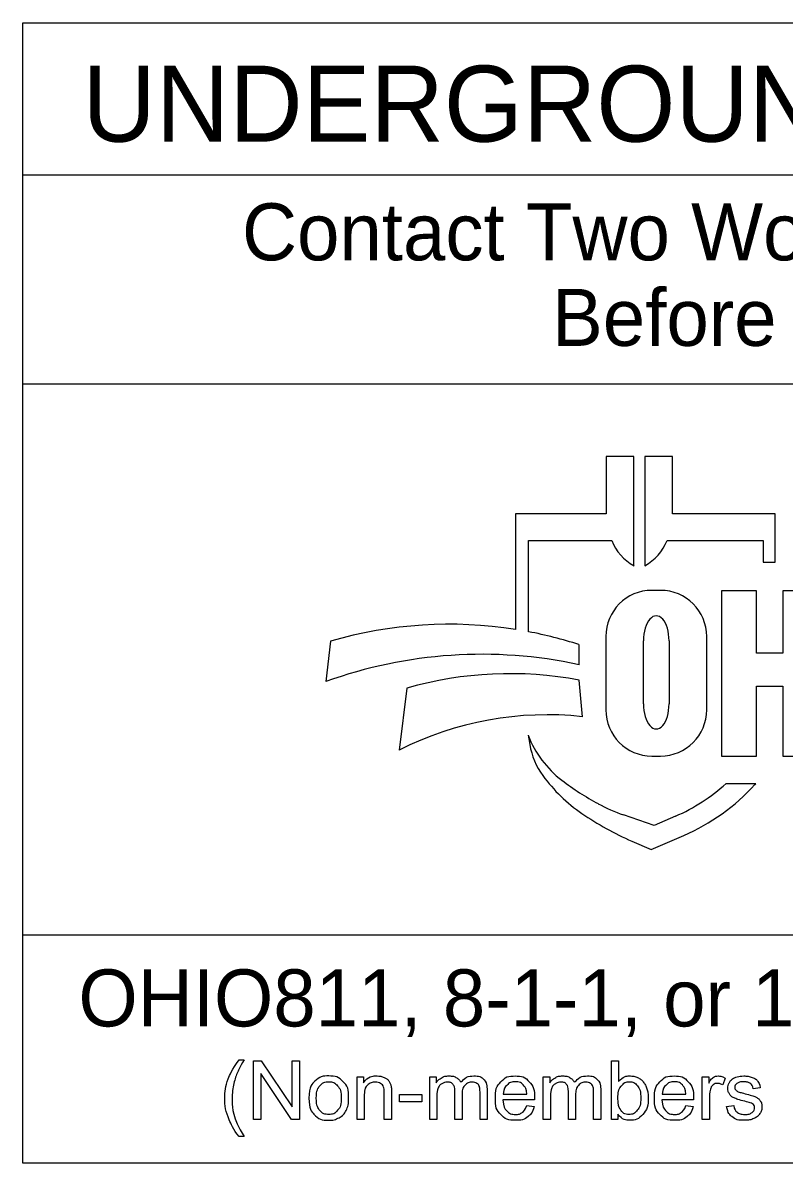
# Model space of a CAD drawing. Extents: x 0 to 34, y 0 to 22.
# Drawn here: x 3.242 to 5.246, y 2.235 to 5.235 of the extents above; entities that cross this region are included whole.
import ezdxf

# ---------------------------------------------------------------- set-up
doc = ezdxf.new("R2010")
doc.units = 0
doc.layers.add('SH_Data', color=7, linetype='Continuous')

msp = doc.modelspace()

# ---------------------------------------------------------------- linework, layer by layer
at = {"layer": 'SH_Data'}
for p, q in [((3.2423, 5.2348), (7.9923, 5.2348)), ((3.2423, 2.2348), (3.2423, 5.2348)), ((3.2423, 4.8348), (7.9923, 4.8348)), ((3.2423, 4.2848), (7.9923, 4.2848)), ((4.8504, 4.0943), (4.7776, 4.0943)), ((4.7776, 4.0943), (4.7776, 3.9429)), ((4.8504, 3.8063), (4.8504, 4.0943)), ((4.9515, 4.0943), (4.8787, 4.0943)), ((4.8787, 4.0943), (4.8787, 3.8063)), ((4.9515, 3.9429), (4.9515, 4.0943)), ((4.7776, 3.9429), (4.5386, 3.9429)), ((4.5386, 3.9429), (4.5386, 3.6389)), ((5.2221, 3.9429), (4.9515, 3.9429)), ((5.2221, 3.8155), (5.2221, 3.9429)), ((4.5729, 3.6329), (4.5729, 3.873)), ((4.5729, 3.873), (4.7917, 3.873)), ((4.9374, 3.873), (5.1905, 3.873)), ((5.1905, 3.873), (5.1905, 3.8155)), ((5.1905, 3.8155), (5.2221, 3.8155)), ((4.9202, 3.7418), (4.8977, 3.7418)), ((5.1728, 3.7405), (5.0805, 3.7405)), ((5.0805, 3.7405), (5.0805, 3.3059)), ((4.0522, 3.6078), (4.0395, 3.5017)), ((4.7762, 3.6203), (4.7762, 3.4274)), ((4.8752, 3.4429), (4.8752, 3.6091)), ((4.9428, 3.6091), (4.9428, 3.4429)), ((5.0417, 3.4274), (5.0417, 3.6203)), ((4.7058, 3.5462), (4.7058, 3.599)), ((4.2528, 3.4848), (4.2328, 3.3217)), ((4.715, 3.4094), (4.7065, 3.5058)), ((5.1728, 3.3059), (5.1728, 3.4897)), ((4.572, 3.3606), (4.5762, 3.3363)), ((4.8977, 3.3059), (4.9202, 3.3059)), ((5.0805, 3.3059), (5.1728, 3.3059)), ((5.1706, 3.2332), (5.0926, 3.2332)), ((5.1684, 3.2308), (5.1706, 3.2332)), ((4.9038, 3.1234), (4.8231, 3.1512)), ((4.9596, 3.1476), (4.9038, 3.1234)), ((4.8957, 3.0596), (4.9816, 3.0968)), ((4.8449, 3.0819), (4.8957, 3.0596)), ((7.9923, 2.8348), (3.2423, 2.8348)), ((7.9923, 2.2348), (3.2423, 2.2348))]:
    msp.add_line(p, q, dxfattribs=at)
for points in [[(5.1728, 3.4897), (5.242, 3.4897), (5.242, 3.3059), (5.3343, 3.3059), (5.3343, 3.7405), (5.242, 3.7405), (5.242, 3.5766), (5.1728, 3.5766), (5.1728, 3.7405)], [(3.8112, 2.5067), (3.8247, 2.5067)], [(3.8489, 2.3501), (3.8489, 2.5041), (3.8698, 2.5041), (3.9508, 2.3832), (3.9508, 2.5041), (3.9703, 2.5041), (3.9703, 2.3501), (3.9494, 2.3501), (3.8684, 2.4711), (3.8684, 2.3501), (3.8489, 2.3501)], [(4.8083, 2.3501), (4.7909, 2.3501), (4.7909, 2.5041), (4.8098, 2.5041), (4.8098, 2.4493)], [(4.1217, 2.3501), (4.1217, 2.4618), (4.1387, 2.4618), (4.1387, 2.4459)], [(4.3129, 2.3501), (4.3129, 2.4618), (4.3298, 2.4618), (4.3298, 2.446)], [(4.6117, 2.3501), (4.6117, 2.4618), (4.6286, 2.4618), (4.6286, 2.446)], [(5.03, 2.3501), (5.03, 2.4618), (5.047, 2.4618), (5.047, 2.4449)], [(5.0905, 2.4582), (5.0839, 2.4407)], [(5.1828, 2.4329), (5.1642, 2.4304)], [(4.1406, 2.411), (4.1406, 2.3501), (4.1217, 2.3501)], [(4.2123, 2.4187), (4.2123, 2.3501), (4.1934, 2.3501), (4.1934, 2.418)], [(4.2338, 2.3964), (4.2338, 2.4154), (4.292, 2.4154), (4.292, 2.3964), (4.2338, 2.3964)], [(4.3318, 2.408), (4.3318, 2.3501), (4.3129, 2.3501)], [(4.3981, 2.4149), (4.3981, 2.3501), (4.3792, 2.3501), (4.3792, 2.4226)], [(4.4642, 2.4267), (4.4642, 2.3501), (4.4453, 2.3501), (4.4453, 2.4204)], [(4.5885, 2.4011), (4.5053, 2.4011)], [(4.5063, 2.4166), (4.5687, 2.4166)], [(4.6306, 2.408), (4.6306, 2.3501), (4.6117, 2.3501)], [(4.6969, 2.4149), (4.6969, 2.3501), (4.678, 2.3501), (4.678, 2.4226)], [(4.763, 2.4267), (4.763, 2.3501), (4.7441, 2.3501), (4.7441, 2.4204)], [(5.007, 2.4011), (4.9237, 2.4011)], [(4.9248, 2.4166), (4.9871, 2.4166)], [(5.0489, 2.4086), (5.0489, 2.3501), (5.03, 2.3501)], [(4.5684, 2.3862), (4.588, 2.3837)], [(4.9869, 2.3862), (5.0064, 2.3837)], [(5.0942, 2.3835), (5.1128, 2.3864)], [(4.8083, 2.3641), (4.8083, 2.3501)], [(3.8247, 2.3048), (3.8112, 2.3048)]]:
    msp.add_lwpolyline(points, dxfattribs=at)
for centre, radius, start, end in [((4.9158, 3.923), 0.1337, 201.9296, 240.7469), ((4.8133, 3.923), 0.1337, 299.2531, 338.0704), ((4.8977, 3.6203), 0.1215, 90, 180), ((4.9202, 3.6203), 0.1215, 0, 90), ((4.3646, 2.5403), 1.1123, 81.0007, 106.3144), ((4.3646, 2.5403), 1.1123, 72.1402, 79.2074), ((4.4503, 2.3622), 1.2113, 77.8238, 109.8274), ((4.5243, 2.5283), 0.9943, 79.44, 105.8467), ((4.8977, 3.4274), 0.1215, 180, 270), ((4.9202, 3.4274), 0.1215, 270, 0), ((4.6221, 2.5511), 0.8633, 83.8248, 116.8021), ((4.8265, 3.4585), 0.2727, 201.0457, 232.5314), ((4.7681, 3.369), 0.1947, 189.6817, 216.0884), ((4.9496, 3.5013), 0.4193, 216.0884, 235.7167), ((5.088, 3.7997), 0.7025, 232.5314, 241.794), ((4.7648, 3.5964), 0.4892, 293.4582, 312.0712), ((4.7648, 3.5964), 0.5445, 293.4582, 317.8286), ((4.9723, 3.584), 0.4578, 241.794, 250.9821), ((5.1757, 3.833), 0.8207, 235.7167, 246.2325)]:
    msp.add_arc(centre, radius, start, end, dxfattribs=at)
for centre, start_param, end_param in [((4.909, 3.6091), 4.712389, 7.853982), ((4.909, 3.4429), 1.570796, 4.712389)]:
    msp.add_ellipse(centre, major_axis=(0, 0.0657), ratio=0.514403, start_param=start_param, end_param=end_param, dxfattribs=at)
for points in [[(3.8112, 2.3048), (3.7956, 2.3246), (3.7847, 2.3511), (3.7739, 2.3775), (3.7739, 2.4059), (3.7739, 2.4309), (3.782, 2.4538), (3.7915, 2.4804), (3.8112, 2.5067)], [(3.8247, 2.5067), (3.812, 2.4849), (3.8079, 2.4755), (3.8016, 2.461), (3.7979, 2.4453), (3.7934, 2.4256), (3.7934, 2.4058), (3.7934, 2.3553), (3.8247, 2.3048)], [(3.995, 2.406), (3.995, 2.4369), (4.0123, 2.4518), (4.0266, 2.4642), (4.0473, 2.4642), (4.0703, 2.4642), (4.0849, 2.4492), (4.0995, 2.4341), (4.0995, 2.4075), (4.0995, 2.386), (4.093, 2.3737), (4.0866, 2.3613), (4.0743, 2.3545), (4.0619, 2.3477), (4.0473, 2.3477), (4.0239, 2.3477), (4.0095, 2.3627), (3.995, 2.3777), (3.995, 2.406)], [(4.1387, 2.4459), (4.151, 2.4642), (4.1742, 2.4642), (4.1843, 2.4642), (4.1927, 2.4606), (4.2012, 2.457), (4.2054, 2.4511), (4.2096, 2.4452), (4.2113, 2.4371), (4.2123, 2.4319), (4.2123, 2.4187)], [(4.3298, 2.446), (4.335, 2.4542), (4.3438, 2.4592), (4.3525, 2.4642), (4.3636, 2.4642), (4.376, 2.4642), (4.384, 2.4591), (4.3919, 2.4539), (4.3952, 2.4446), (4.4084, 2.4642), (4.4297, 2.4642), (4.4463, 2.4642), (4.4552, 2.455), (4.4642, 2.4458), (4.4642, 2.4267)], [(4.588, 2.3837), (4.5834, 2.3666), (4.5709, 2.3571), (4.5584, 2.3477), (4.5389, 2.3477), (4.5145, 2.3477), (4.5001, 2.3627), (4.4858, 2.3778), (4.4858, 2.405), (4.4858, 2.4332), (4.5003, 2.4487), (4.5148, 2.4642), (4.5379, 2.4642), (4.5603, 2.4642), (4.5744, 2.449), (4.5886, 2.4338), (4.5886, 2.4061), (4.5886, 2.4044), (4.5885, 2.4011)], [(4.6286, 2.446), (4.6339, 2.4542), (4.6426, 2.4592), (4.6513, 2.4642), (4.6625, 2.4642), (4.6749, 2.4642), (4.6828, 2.4591), (4.6907, 2.4539), (4.694, 2.4446), (4.7073, 2.4642), (4.7285, 2.4642), (4.7451, 2.4642), (4.7541, 2.455), (4.763, 2.4458), (4.763, 2.4267)], [(4.8098, 2.4493), (4.8217, 2.4642), (4.8403, 2.4642), (4.8506, 2.4642), (4.8598, 2.4601), (4.869, 2.4559), (4.8749, 2.4484), (4.8809, 2.4409), (4.8842, 2.4303), (4.8876, 2.4197), (4.8876, 2.4076), (4.8876, 2.379), (4.8734, 2.3633), (4.8592, 2.3477), (4.8393, 2.3477), (4.8196, 2.3477), (4.8083, 2.3641)], [(5.0064, 2.3837), (5.0018, 2.3666), (4.9893, 2.3571), (4.9768, 2.3477), (4.9574, 2.3477), (4.9329, 2.3477), (4.9186, 2.3627), (4.9042, 2.3778), (4.9042, 2.405), (4.9042, 2.4332), (4.9187, 2.4487), (4.9332, 2.4642), (4.9563, 2.4642), (4.9787, 2.4642), (4.9929, 2.449), (5.0071, 2.4338), (5.0071, 2.4061), (5.0071, 2.4044), (5.007, 2.4011)], [(5.047, 2.4449), (5.0535, 2.4567), (5.059, 2.4605), (5.0645, 2.4642), (5.0711, 2.4642), (5.0807, 2.4642), (5.0905, 2.4582)], [(5.1128, 2.3864), (5.1144, 2.3752), (5.1216, 2.3692), (5.1288, 2.3632), (5.1418, 2.3632), (5.1549, 2.3632), (5.1612, 2.3685), (5.1675, 2.3738), (5.1675, 2.381), (5.1675, 2.3874), (5.1619, 2.3911), (5.158, 2.3936), (5.1426, 2.3975), (5.1217, 2.4027), (5.1137, 2.4066), (5.1056, 2.4104), (5.1015, 2.4172), (5.0973, 2.4239), (5.0973, 2.4321), (5.0973, 2.4396), (5.1008, 2.4459), (5.1042, 2.4523), (5.1101, 2.4565), (5.1145, 2.4597), (5.1221, 2.462), (5.1297, 2.4642), (5.1385, 2.4642), (5.1516, 2.4642), (5.1616, 2.4604), (5.1715, 2.4567), (5.1763, 2.4502), (5.181, 2.4437), (5.1828, 2.4329)], [(4.0145, 2.4059), (4.0145, 2.3845), (4.0238, 2.3738), (4.0332, 2.3632), (4.0473, 2.3632), (4.0614, 2.3632), (4.0707, 2.3739), (4.08, 2.3846), (4.08, 2.4066), (4.08, 2.4273), (4.0706, 2.438), (4.0613, 2.4486), (4.0473, 2.4486), (4.0332, 2.4486), (4.0238, 2.438), (4.0145, 2.4274), (4.0145, 2.4059)], [(4.1934, 2.418), (4.1934, 2.4295), (4.1912, 2.4353), (4.189, 2.441), (4.1834, 2.4444), (4.1778, 2.4478), (4.1702, 2.4478), (4.1581, 2.4478), (4.1494, 2.4401), (4.1406, 2.4325), (4.1406, 2.411)], [(4.3792, 2.4226), (4.3792, 2.4352), (4.3746, 2.4415), (4.3699, 2.4478), (4.3594, 2.4478), (4.3514, 2.4478), (4.3447, 2.4436), (4.3379, 2.4394), (4.3348, 2.4313), (4.3318, 2.4232), (4.3318, 2.408)], [(4.4453, 2.4204), (4.4453, 2.4317), (4.4434, 2.4367), (4.4416, 2.4417), (4.4368, 2.4448), (4.4319, 2.4478), (4.4254, 2.4478), (4.4136, 2.4478), (4.4059, 2.44), (4.3981, 2.4322), (4.3981, 2.4149)], [(4.5687, 2.4166), (4.5674, 2.4307), (4.5615, 2.4378), (4.5525, 2.4487), (4.5381, 2.4487), (4.525, 2.4487), (4.5162, 2.44), (4.5073, 2.4312), (4.5063, 2.4166)], [(4.678, 2.4226), (4.678, 2.4352), (4.6734, 2.4415), (4.6688, 2.4478), (4.6583, 2.4478), (4.6503, 2.4478), (4.6435, 2.4436), (4.6367, 2.4394), (4.6337, 2.4313), (4.6306, 2.4232), (4.6306, 2.408)], [(4.7441, 2.4204), (4.7441, 2.4317), (4.7423, 2.4367), (4.7404, 2.4417), (4.7356, 2.4448), (4.7308, 2.4478), (4.7243, 2.4478), (4.7125, 2.4478), (4.7047, 2.44), (4.6969, 2.4322), (4.6969, 2.4149)], [(4.8081, 2.4068), (4.8081, 2.3867), (4.8136, 2.3778), (4.8225, 2.3632), (4.8377, 2.3632), (4.8501, 2.3632), (4.8591, 2.3739), (4.8681, 2.3847), (4.8681, 2.4061), (4.8681, 2.4279), (4.8594, 2.4383), (4.8508, 2.4487), (4.8385, 2.4487), (4.8261, 2.4487), (4.8171, 2.438), (4.8081, 2.4272), (4.8081, 2.4068)], [(4.9871, 2.4166), (4.9859, 2.4307), (4.98, 2.4378), (4.9709, 2.4487), (4.9565, 2.4487), (4.9435, 2.4487), (4.9346, 2.44), (4.9257, 2.4312), (4.9248, 2.4166)], [(5.0839, 2.4407), (5.077, 2.4447), (5.0701, 2.4447), (5.0639, 2.4447), (5.059, 2.441), (5.0541, 2.4373), (5.052, 2.4307), (5.0489, 2.4206), (5.0489, 2.4086)], [(5.1642, 2.4304), (5.163, 2.4391), (5.1569, 2.4439), (5.1509, 2.4487), (5.1398, 2.4487), (5.1268, 2.4487), (5.1212, 2.4444), (5.1156, 2.4401), (5.1156, 2.4343), (5.1156, 2.4306), (5.118, 2.4277), (5.1203, 2.4246), (5.1252, 2.4226), (5.1281, 2.4216), (5.1419, 2.4178), (5.162, 2.4124), (5.17, 2.409), (5.1779, 2.4056), (5.1825, 2.3991), (5.187, 2.3926), (5.187, 2.3829), (5.187, 2.3735), (5.1815, 2.3652), (5.176, 2.3568), (5.1655, 2.3522), (5.1551, 2.3477), (5.142, 2.3477), (5.1202, 2.3477), (5.1087, 2.3567), (5.0973, 2.3657), (5.0942, 2.3835)], [(4.5053, 2.4011), (4.5063, 2.3827), (4.5157, 2.3729), (4.525, 2.3632), (4.539, 2.3632), (4.5494, 2.3632), (4.5568, 2.3687), (4.5641, 2.3741), (4.5684, 2.3862)], [(4.9237, 2.4011), (4.9248, 2.3827), (4.9341, 2.3729), (4.9435, 2.3632), (4.9575, 2.3632), (4.9679, 2.3632), (4.9752, 2.3687), (4.9826, 2.3741), (4.9869, 2.3862)]]:
    msp.add_open_spline(points, degree=3, dxfattribs=at)

# ---------------------------------------------------------------- texts
for s, height, p in [('UNDERGROUND UTILITIES', 0.2, (3.3992, 4.9221)), ('Contact Two Working Days', 0.15, (3.819, 4.6099)), ('Before You Dig', 0.15, (4.6346, 4.3849)), ('OHIO811, 8-1-1, or 1-800-362-2764', 0.15, (3.3887, 2.5946))]:
    msp.add_text(s, height=height, dxfattribs=at).set_placement(p)

doc.saveas('drawing.dxf')
